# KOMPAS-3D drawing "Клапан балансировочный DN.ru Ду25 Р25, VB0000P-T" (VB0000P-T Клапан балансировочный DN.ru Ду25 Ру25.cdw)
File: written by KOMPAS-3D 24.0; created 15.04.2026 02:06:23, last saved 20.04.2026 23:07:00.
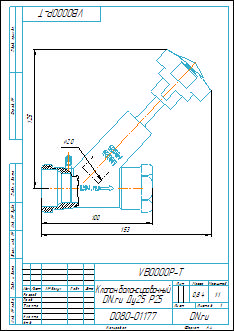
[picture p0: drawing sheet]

Document properties: Автор: DN.ru; Форматы листов документа: A4; Полное имя файла: VB0000P-T Клапан балансировочный DN.ru Ду25 Ру25.m3d; Масса: 0.84; Наименование: Клапан балансировочный DN.ru Ду25 Р25; Количество листов документа: 1; Примечание: D080-01177

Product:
- Part/product: Клапан балансировочный DN.ru Ду25 Р25  | designation VB0000P-T
    Масса: 0.84
    Раздел спецификации: Прочие изделия
    Примечание: D080-01177

Views: Вид 1, Местный разрез 1, Вид:1
Referenced files in C:\Работа\VB0000P-T DN X PN 25 Клапан балансировочный DN.ru\DN15\: VB0000P-T DN15 PN25 Клапан балансировочный DN.ru.m3d
Referenced files in E:\Работа\Зайцев\АУТСОРС\Диман\Балансировка\VB0000P-T Клапан балансировочный DN.ru Ду15-50 Ру25\DN25\: VB0000P-T Клапан балансировочный DN.ru Ду25 Ру25.m3d
Referenced files in C:\Program Files\ASCON\KOMPAS-3D v24\Templates\: Чертеж_DN.ru.cdt
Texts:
  VB0000P-T
  Чертеж_DN.ru.cdt
  Клапан балансировочный
  DN.ru Ду25 Р25
  Клапан балансировочный DN.ru Ду25 Р25
  VB0000P-T Клапан балансировочный DN.ru Ду25 Р25
Dimensions and other numbers on the sheet: 0; 3; 2; 4; 100; 125; 153; 1:1; 1; 0,84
